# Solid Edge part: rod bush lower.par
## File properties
Author: Robert a Rhodes jr
Template: Normal.par
Last saved by: CADCIM
Revision: 4
Application: Solid Edge
Accuracy: 0.99
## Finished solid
Body 1: solid body, 4 faces, 4 edges, 0 vertices.
  Faces by surface: cylinder 2, plane 2
  Edges by curve: circle 4
Bounding box of the edges (mm): 15.000 x 15.000 x 24.000, from (-7.5, -7.5, -24) to (7.5, 7.5, 0).
Cylindrical faces by radius (mm): R6 x1, R7.5 x1
Planar faces by outward normal: +z 1, -z 1
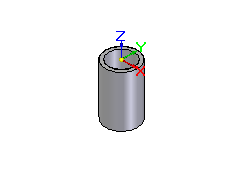
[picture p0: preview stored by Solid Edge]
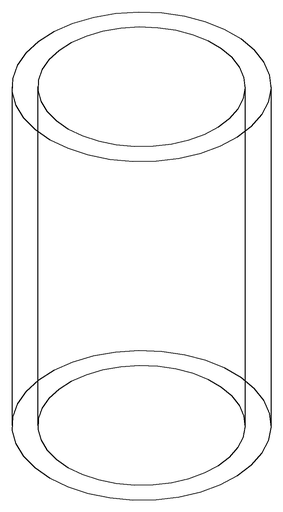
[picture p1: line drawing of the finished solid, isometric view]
